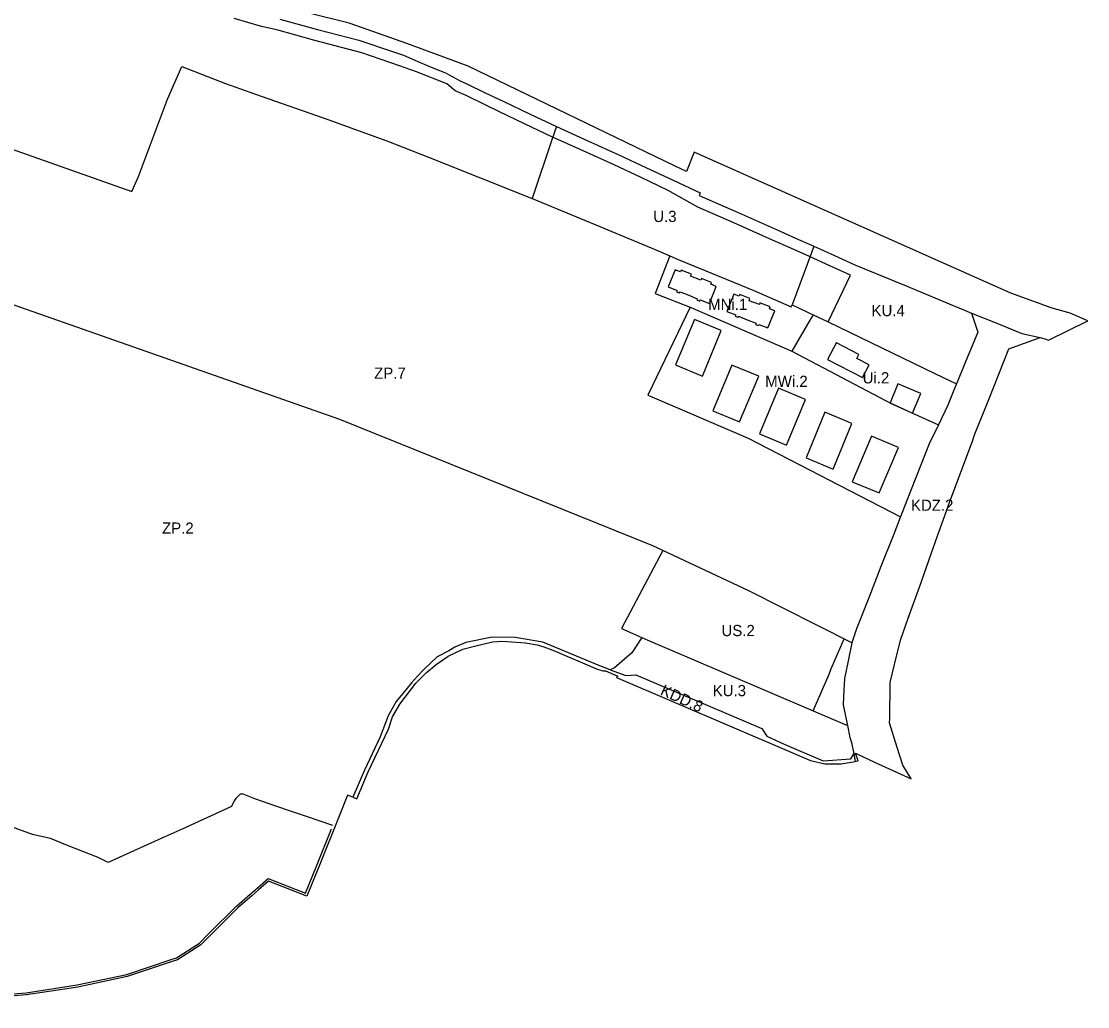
# Model space of a CAD drawing. Extents: x 7427219 to 7428976, y 5542673 to 5543767.
# Drawn here: x 7428500.8 to 7428976.3, y 5542971.5 to 5543410.7 of the extents above; entities that cross this region are included whole.
import ezdxf

# ---------------------------------------------------------------- set-up
doc = ezdxf.new("R2010")
doc.units = 0
for name, color, linetype in [('linie rozgraniczające', 7, 'Continuous'), ('nieprzekraczalna_linia_lokalizacyjna', 7, 'Continuous'), ('nieprzekraczalne linie zabudowy', 7, 'Continuous'), ('obowiazujace linie zabudowy', 7, 'Continuous'), ('przeznaczenia terenów', 7, 'Continuous')]:
    doc.layers.add(name, color=color, linetype=linetype)

msp = doc.modelspace()

# ---------------------------------------------------------------- linework, layer by layer
at = {"layer": 'linie rozgraniczające'}
for points in [[(7428955.18, 5543269.67), (7428957.17, 5543269.08), (7428958.88, 5543268.54), (7428976.29, 5543277.15), (7428968.53, 5543280.57), (7428960.48, 5543282.86), (7428942.01, 5543289.47), (7428800.87, 5543352.36), (7428797.41, 5543343.78), (7428792.41, 5543346.08), (7428699.97, 5543390.65), (7428672.76, 5543400.83), (7428647, 5543409.84), (7428609.24, 5543419.25), (7428450.4, 5543449.31), (7428417.15, 5543461.01), (7428379.61, 5543471.46), (7428345.06, 5543473.61), (7428320.11, 5543472.52), (7428305.29, 5543471.75), (7428246.28, 5543471.97), (7428240.89, 5543471.99), (7428238.59, 5543465.57)], [(7428616, 5543411.66), (7428632.9, 5543406.99), (7428651.22, 5543402.21), (7428667.15, 5543396.89), (7428671.22, 5543395.52), (7428678.61, 5543392.25), (7428684.27, 5543390), (7428689.92, 5543387.74), (7428693.2, 5543385.95), (7428696.48, 5543384.15), (7428699.47, 5543382.75), (7428707.68, 5543378.83), (7428715.89, 5543374.92), (7428727.65, 5543369.32), (7428739.4, 5543363.71), (7428753.33, 5543357.46), (7428767.27, 5543351.22), (7428779.25, 5543345.57), (7428791.42, 5543339.84), (7428803.47, 5543334.16), (7428803.07, 5543333.02), (7428820.46, 5543325.38), (7428837.84, 5543317.75), (7428846.04, 5543314.06), (7428854.23, 5543310.37), (7428863.37, 5543306.26), (7428872.51, 5543302.15), (7428895.28, 5543292.71), (7428918.04, 5543283.27), (7428921.29, 5543281.93), (7428924.53, 5543280.59)], [(7428424.62, 5543379.08), (7428550.06, 5543334.85), (7428552.96, 5543341.48), (7428566.03, 5543376.03), (7428572.28, 5543390.46), (7428591.82, 5543382.99), (7428605.27, 5543378.23), (7428638.3, 5543366.56), (7428652.64, 5543361.4), (7428663.71, 5543357.34), (7428682.29, 5543350.17), (7428704.41, 5543341.37), (7428728.58, 5543331.73), (7428756.98, 5543320.02), (7428769.38, 5543314.82)], [(7428739.4, 5543363.71), (7428737.56, 5543358.27), (7428728.58, 5543331.73)], [(7428786.81, 5543174.75), (7428782.31, 5543176.85), (7428642.74, 5543233.24), (7428497.53, 5543284.1), (7428478.49, 5543293.06), (7428431.56, 5543307.52), (7428405.35, 5543315.6)], [(7428769.38, 5543314.82), (7428781.67, 5543309.69), (7428790, 5543306.2), (7428793.7, 5543304.53), (7428827.46, 5543290.71), (7428844.12, 5543283.45), (7428844.59, 5543284.29), (7428853.85, 5543279.9), (7428860.55, 5543276.74), (7428908.09, 5543253.73), (7428917.79, 5543249.05)], [(7428854.23, 5543310.37), (7428853.24, 5543307.93), (7428844.59, 5543284.29)], [(7428790, 5543306.2), (7428783.48, 5543289.27), (7428799.03, 5543283.18), (7428780.13, 5543243.96)], [(7428799.03, 5543283.18), (7428844.38, 5543263.64), (7428888.93, 5543240.17), (7428909.7, 5543230.84)], [(7428853.85, 5543279.9), (7428852.41, 5543277.42), (7428844.38, 5543263.64)], [(7428924.53, 5543280.59), (7428927.31, 5543272.17), (7428922.55, 5543260.61), (7428917.79, 5543249.05)], [(7428924.53, 5543280.59), (7428935.74, 5543276.08), (7428946.94, 5543271.58), (7428955.18, 5543269.67)], [(7428872.61, 5543080.76), (7428872.99, 5543080.82), (7428873.95, 5543080.98), (7428872.71, 5543084.4), (7428881.29, 5543080.5), (7428897.56, 5543073.04), (7428893.84, 5543079.08), (7428891.4, 5543086.95), (7428887.99, 5543097.92), (7428888.01, 5543099.69), (7428888.19, 5543115.97), (7428890.14, 5543123.97), (7428892.78, 5543134.79), (7428896.3, 5543144.66), (7428901.39, 5543158.92), (7428906.5, 5543173.27), (7428909.36, 5543181.26), (7428911.89, 5543188.37), (7428914.69, 5543196.21), (7428925.11, 5543223.92), (7428925.88, 5543226.41), (7428932.15, 5543242.14), (7428941.14, 5543264.7), (7428955.18, 5543269.67)], [(7428917.79, 5543249.05), (7428916.63, 5543246.21), (7428913.86, 5543239.51), (7428909.7, 5543230.84), (7428905.61, 5543222.33), (7428895.69, 5543197.12), (7428892.81, 5543189.81)], [(7428780.13, 5543243.96), (7428780.86, 5543243.66), (7428824.95, 5543224.87), (7428892.81, 5543189.81)], [(7428892.81, 5543189.81), (7428892.71, 5543189.56), (7428889.8, 5543182.13), (7428884.11, 5543167.68), (7428878.63, 5543153.74), (7428873.26, 5543139.83), (7428872.17, 5543136.73), (7428871.07, 5543133.62)], [(7428871.07, 5543133.62), (7428825.15, 5543156.86), (7428786.81, 5543174.75), (7428781.37, 5543164.37), (7428768.43, 5543139.95), (7428777.49, 5543136.04)], [(7428763.41, 5543121.63), (7428758.06, 5543123.63), (7428733.27, 5543133.96), (7428720.93, 5543136.07), (7428710.81, 5543136.12), (7428699.03, 5543133.84), (7428694.04, 5543131.75), (7428691.35, 5543130.11), (7428686.25, 5543127.45), (7428680.34, 5543121.68), (7428677.42, 5543118.83), (7428674.77, 5543115.85), (7428672.23, 5543112.75), (7428667.9, 5543107.46), (7428664.4, 5543101.05), (7428660.74, 5543091.8), (7428653.84, 5543076.83), (7428648.56, 5543064.78)], [(7428648.56, 5543064.78), (7428650.39, 5543064.09), (7428655.43, 5543076.12), (7428664.44, 5543095.14), (7428666.27, 5543100.68), (7428669.5, 5543106.28), (7428676.76, 5543115.58), (7428681.53, 5543120.34), (7428685.78, 5543124.01), (7428691.05, 5543127.75), (7428697.66, 5543130.83), (7428702.86, 5543132.09), (7428710.89, 5543134.03), (7428715.17, 5543134.4), (7428725.58, 5543133.69), (7428730.83, 5543132.72), (7428733.76, 5543131.84), (7428737.72, 5543130.35), (7428757.28, 5543121.98), (7428760.11, 5543121.16), (7428761.32, 5543121.16), (7428766.77, 5543118.79), (7428766.24, 5543118.22), (7428843.29, 5543085.12), (7428852.74, 5543081.11), (7428859.06, 5543079.71), (7428866.31, 5543079.75), (7428872.61, 5543080.76)], [(7428777.49, 5543136.04), (7428773.04, 5543129.21), (7428768.55, 5543125.25), (7428765.24, 5543122.5), (7428763.41, 5543121.63)], [(7428777.49, 5543136.04), (7428780.13, 5543134.85), (7428869.15, 5543096.76)], [(7428871.07, 5543133.62), (7428869.47, 5543125.67), (7428867.87, 5543117.71), (7428867.48, 5543109.67), (7428867.3, 5543105.99), (7428868.16, 5543101.73), (7428869.02, 5543097.46), (7428869.15, 5543096.76)], [(7428763.41, 5543121.63), (7428770.27, 5543119.07), (7428774.87, 5543119.37), (7428831.06, 5543095.45), (7428833.19, 5543091.97), (7428840.98, 5543088.47), (7428858.28, 5543081.06), (7428870.62, 5543081.87), (7428871.96, 5543084.17)], [(7428869.15, 5543096.76), (7428870.23, 5543091.37), (7428870.98, 5543089.27), (7428871.96, 5543084.17)], [(7428871.96, 5543084.17), (7428872.61, 5543080.76)], [(7428648.56, 5543064.78), (7428646.2, 5543065.67), (7428642.46, 5543056.38), (7428633.38, 5543033.78), (7428628.13, 5543020.74), (7428611.06, 5543027.39), (7428606.54, 5543023.46), (7428603.51, 5543020.81), (7428597.39, 5543015.48), (7428585.17, 5543003.28), (7428580.9, 5542999.01), (7428570.35, 5542992.3), (7428567.98, 5542991.51), (7428548.03, 5542984.89), (7428525.91, 5542980.19), (7428503.12, 5542976.68), (7428466.55, 5542973.8), (7428436.8, 5542971.45), (7428377.22, 5542993.3), (7428352.34, 5543003.23)]]:
    msp.add_lwpolyline(points, dxfattribs=at)
at = {"layer": 'nieprzekraczalna_linia_lokalizacyjna'}
for points in [[(7428639.71, 5543052.21), (7428628, 5543056.18), (7428620.39, 5543058.8), (7428614.75, 5543060.68), (7428604.89, 5543064.16), (7428599.77, 5543066.13), (7428599.43, 5543066.25), (7428599.01, 5543066.24), (7428598.53, 5543066.13), (7428598.2, 5543065.97), (7428597.41, 5543065.3), (7428596.46, 5543064.19), (7428595.86, 5543063.42), (7428595.18, 5543062.25), (7428594.46, 5543060.64)], [(7428513.76, 5543046.43), (7428506.33, 5543048.01), (7428505.73, 5543048.26), (7428498.02, 5543050.96), (7428489.62, 5543053.95), (7428477.68, 5543058.35)], [(7428594.46, 5543060.64), (7428572.74, 5543050.73), (7428564.8, 5543047.1), (7428551.02, 5543040.88), (7428539.57, 5543035.73)], [(7428353.64, 5543003.78), (7428377.58, 5542994.23), (7428436.94, 5542972.46), (7428466.47, 5542974.8), (7428503, 5542977.67), (7428525.73, 5542981.17), (7428547.77, 5542985.86), (7428567.66, 5542992.46), (7428569.92, 5542993.21), (7428580.27, 5542999.79), (7428584.46, 5543003.99), (7428596.71, 5543016.21), (7428602.85, 5543021.56), (7428605.88, 5543024.21), (7428610.86, 5543028.54), (7428627.57, 5543022.03), (7428632.45, 5543034.15), (7428639.08, 5543050.65)], [(7428539.57, 5543035.73), (7428535.08, 5543037.99), (7428521.43, 5543043.29), (7428513.76, 5543046.43)]]:
    msp.add_lwpolyline(points, dxfattribs=at)
at = {"layer": 'nieprzekraczalne linie zabudowy'}
for points in [[(7428860.55, 5543276.74), (7428870.53, 5543297.56), (7428861.32, 5543301.7), (7428852.18, 5543305.81), (7428843.98, 5543309.5), (7428835.81, 5543313.18), (7428818.44, 5543320.81), (7428802.38, 5543327.86), (7428789.29, 5543335.32), (7428777.12, 5543341.05), (7428765.18, 5543346.68), (7428751.29, 5543352.9), (7428737.3, 5543359.17), (7428725.49, 5543364.8), (7428713.74, 5543370.41), (7428707.37, 5543373.64), (7428699.19, 5543377.58), (7428694.22, 5543379.69), (7428690.58, 5543382.81), (7428677.02, 5543388.14), (7428669.41, 5543390.85), (7428661.29, 5543393.6), (7428652.68, 5543396.61), (7428631.6, 5543402.16), (7428614.77, 5543406.81), (7428607.95, 5543408.38), (7428595.68, 5543411.9)], [(7428853.85, 5543103.31), (7428860.99, 5543119.69), (7428861.83, 5543121.69), (7428867.65, 5543135.35)]]:
    msp.add_lwpolyline(points, dxfattribs=at)
at = {"layer": 'obowiazujace linie zabudowy'}
for points in [[(7428792.31, 5543299.94), (7428789.23, 5543292.29), (7428793.17, 5543290.7), (7428792.95, 5543290.15), (7428794.3, 5543289.61), (7428794.5, 5543290.12), (7428798.37, 5543288.57), (7428802.22, 5543287.03), (7428801.99, 5543286.46), (7428803.33, 5543285.92), (7428803.55, 5543286.46), (7428807.6, 5543284.81), (7428810.58, 5543292.48), (7428808.26, 5543293.43), (7428808.59, 5543294.27), (7428804.05, 5543296.06), (7428803.75, 5543295.31), (7428799.23, 5543297.09), (7428799.57, 5543297.97), (7428794.98, 5543299.74), (7428794.7, 5543299.02)], [(7428815.35, 5543281.36), (7428819.33, 5543279.88), (7428819.08, 5543279.21), (7428820.42, 5543278.7), (7428820.6, 5543279.17), (7428824.5, 5543277.65), (7428828.39, 5543276.13), (7428828.18, 5543275.59), (7428829.5, 5543275.08), (7428829.69, 5543275.56), (7428833.67, 5543273.98), (7428836.78, 5543281.58), (7428834.38, 5543282.52), (7428834.71, 5543283.36), (7428830.17, 5543285.14), (7428829.88, 5543284.4), (7428825.35, 5543286.13), (7428825.7, 5543287.06), (7428821.12, 5543288.9), (7428820.83, 5543288.12), (7428818.46, 5543289)], [(7428800.91, 5543277.82), (7428792.45, 5543257.49), (7428804.49, 5543252.46), (7428812.93, 5543272.84)], [(7428829.6, 5543252.42), (7428817.58, 5543257.43), (7428809.09, 5543237.11), (7428821.09, 5543232.1)], [(7428891.68, 5543249.04), (7428888.19, 5543240.54), (7428898.24, 5543235.96), (7428901.92, 5543244.75)], [(7428838.45, 5543247.16), (7428829.97, 5543226.82), (7428842.01, 5543221.79), (7428850.48, 5543242.14)], [(7428859.15, 5543236.41), (7428850.71, 5543216.08), (7428862.74, 5543211.09), (7428871.18, 5543231.42)], [(7428879.83, 5543225.79), (7428871.34, 5543205.44), (7428883.38, 5543200.42), (7428891.87, 5543220.77)]]:
    msp.add_lwpolyline(points, close=True, dxfattribs=at)
for points in [[(7428864.25, 5543267.43), (7428860.28, 5543259.99), (7428875.86, 5543251.86)], [(7428875.86, 5543251.86), (7428878.83, 5543257.53), (7428873.34, 5543260.4), (7428874.27, 5543262.18), (7428864.25, 5543267.42)]]:
    msp.add_lwpolyline(points, dxfattribs=at)

# ---------------------------------------------------------------- texts
at = {"layer": 'przeznaczenia terenów'}
for s, p in [('U.3', (7428782.56, 5543321.2)), ('MNi.1', (7428807.04, 5543281.97)), ('KU.4', (7428879.91, 5543279.23)), ('ZP.7', (7428658.1, 5543251.33)), ('Ui.2', (7428875.93, 5543249.27)), ('MWi.2', (7428832.5, 5543247.69)), ('KDZ.2', (7428897.48, 5543192.47)), ('ZP.2', (7428563.51, 5543182.27)), ('US.2', (7428813, 5543136.61)), ('KU.3', (7428809.07, 5543109.84))]:
    msp.add_text(s, height=5, dxfattribs=at).set_placement(p)
msp.add_text('KDD.8', height=5, rotation=335.511, dxfattribs=at).set_placement((7428785.36, 5543110.69))

doc.saveas('drawing.dxf')
